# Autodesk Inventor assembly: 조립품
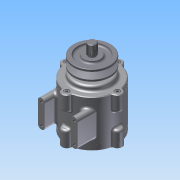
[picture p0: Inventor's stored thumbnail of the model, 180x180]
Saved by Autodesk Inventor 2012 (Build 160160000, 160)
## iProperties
Created: 2015-03
Part Number: 조립품
Document SubType Name: Assembly
Designer: net
Author: net
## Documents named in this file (10)
- C:\Users\net\Desktop\450305V1044\조립품.iam
- C:\Users\net\Desktop\450305V1044\본체.ipt
- C:\Users\net\Desktop\450305V1044\베어링 6204.ipt
- C:\Users\net\Desktop\450305V1044\축.ipt
- C:\Users\net\Desktop\450305V1044\키(4 x 4 x 12).ipt
- C:\Users\net\Desktop\450305V1044\V벨트풀리.ipt
- C:\Users\net\Desktop\450305V1044\커버.ipt
- C:\Users\net\Desktop\450305V1044\커버2.ipt
- C:\Users\net\Desktop\450305V1044\오일실.ipt
- C:\Users\net\Desktop\450305V1044\M 4 x 12.ipt
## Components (13 placed, 5 different names)
1. KS B 2023 6204 - 20 x 47 x 14:1
2. KS B 2023 6204 - 20 x 47 x 14:2
3. KS B 1311 (I) 4 x 4 x 12:1
4. 그루브 풀리1:1
5. KS B 2804 D D - 20 32 8:1
6. KS B 1003 - 미터 M 4 x 12:2
7. KS B 1003 - 미터 M 4 x 12:3
8. KS B 1003 - 미터 M 4 x 12:4
9. KS B 1003 - 미터 M 4 x 12:5
10. KS B 1003 - 미터 M 4 x 12:1
11. KS B 1003 - 미터 M 4 x 12:6
12. KS B 1003 - 미터 M 4 x 12:7
13. KS B 1003 - 미터 M 4 x 12:8
